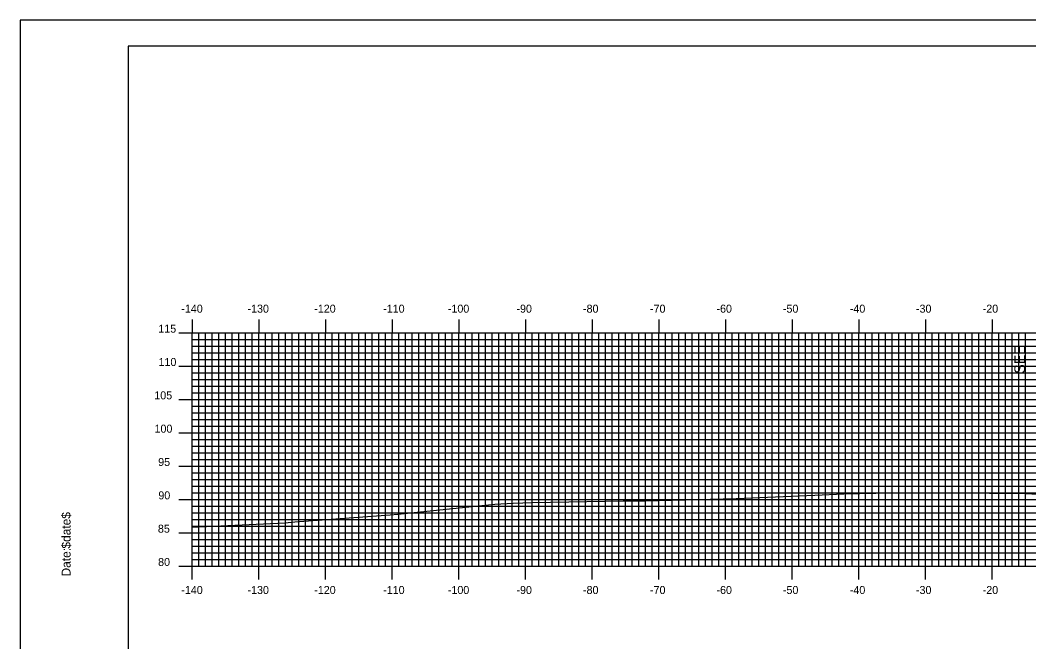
# Model space of a CAD drawing. Extents: x 879 to 1222, y -1658 to -1438.
# Drawn here: x 878.9 to 1030.1, y -1531 to -1437.7 of the extents above; entities that cross this region are included whole.
import ezdxf

# ---------------------------------------------------------------- set-up
doc = ezdxf.new("R2010")
doc.units = 0
for name, color, linetype in [('ANNOTATION', 7, 'Continuous'), ('BORDER', 7, 'Continuous'), ('H_V ANNOTATION', 7, 'Continuous'), ('MAJOR', 7, 'Continuous'), ('MINOR', 7, 'Continuous'), ('PLOT BOUNDARY', 7, 'Continuous'), ('S_Roadway_Centerline', 7, 'Continuous')]:
    doc.layers.add(name, color=color, linetype=linetype)

msp = doc.modelspace()

# ---------------------------------------------------------------- linework, layer by layer
at = {"layer": 'BORDER'}
msp.add_lwpolyline([(895.05, -1651.6), (1215.05, -1651.6), (1215.05, -1441.6), (895.05, -1441.6)], close=True, dxfattribs=at)
at = {"layer": 'MAJOR'}
for p, q in [((904.65, -1482.6), (904.65, -1484.6)), ((914.65, -1482.6), (914.65, -1484.6)), ((924.65, -1482.6), (924.65, -1484.6)), ((934.65, -1482.6), (934.65, -1484.6)), ((944.65, -1482.6), (944.65, -1484.6)), ((954.65, -1482.6), (954.65, -1484.6)), ((964.65, -1482.6), (964.65, -1484.6)), ((974.65, -1482.6), (974.65, -1484.6)), ((984.65, -1482.6), (984.65, -1484.6)), ((994.65, -1482.6), (994.65, -1484.6)), ((1004.65, -1482.6), (1004.65, -1484.6)), ((1014.65, -1482.6), (1014.65, -1484.6)), ((1024.65, -1482.6), (1024.65, -1484.6)), ((902.64, -1484.6), (904.65, -1484.6)), ((904.65, -1484.6), (1184.65, -1484.6)), ((904.65, -1519.6), (904.65, -1484.6)), ((904.65, -1519.6), (904.65, -1484.6)), ((904.65, -1484.6), (1184.65, -1484.6)), ((914.65, -1519.6), (914.65, -1484.6)), ((924.65, -1519.6), (924.65, -1484.6)), ((934.65, -1519.6), (934.65, -1484.6)), ((944.65, -1519.6), (944.65, -1484.6)), ((954.65, -1519.6), (954.65, -1484.6)), ((964.65, -1519.6), (964.65, -1484.6)), ((974.65, -1519.6), (974.65, -1484.6)), ((984.65, -1519.6), (984.65, -1484.6)), ((994.65, -1519.6), (994.65, -1484.6)), ((1004.65, -1519.6), (1004.65, -1484.6)), ((1014.65, -1519.6), (1014.65, -1484.6)), ((1024.65, -1519.6), (1024.65, -1484.6)), ((902.64, -1489.6), (904.65, -1489.6)), ((904.65, -1489.6), (1184.65, -1489.6)), ((902.64, -1494.6), (904.65, -1494.6)), ((904.65, -1494.6), (1184.65, -1494.6)), ((902.64, -1499.6), (904.65, -1499.6)), ((904.65, -1499.6), (1184.65, -1499.6)), ((902.64, -1504.6), (904.65, -1504.6)), ((904.65, -1504.6), (1184.65, -1504.6)), ((902.64, -1509.6), (904.65, -1509.6)), ((904.65, -1509.6), (1184.65, -1509.6)), ((902.64, -1514.6), (904.65, -1514.6)), ((904.65, -1514.6), (1184.65, -1514.6)), ((902.64, -1519.6), (904.65, -1519.6)), ((904.65, -1519.6), (1184.65, -1519.6)), ((904.65, -1519.6), (1184.65, -1519.6)), ((904.65, -1521.61), (904.65, -1519.6)), ((914.65, -1521.61), (914.65, -1519.6)), ((924.65, -1521.61), (924.65, -1519.6)), ((934.65, -1521.61), (934.65, -1519.6)), ((944.65, -1521.61), (944.65, -1519.6)), ((954.65, -1521.61), (954.65, -1519.6)), ((964.65, -1521.61), (964.65, -1519.6)), ((974.65, -1521.61), (974.65, -1519.6)), ((984.65, -1521.61), (984.65, -1519.6)), ((994.65, -1521.61), (994.65, -1519.6)), ((1004.65, -1521.61), (1004.65, -1519.6)), ((1014.65, -1521.61), (1014.65, -1519.6)), ((1024.65, -1521.61), (1024.65, -1519.6))]:
    msp.add_line(p, q, dxfattribs=at)
at = {"layer": 'MINOR'}
for p, q in [((904.65, -1485.6), (1184.65, -1485.6)), ((904.65, -1485.6), (906.65, -1485.6)), ((905.65, -1519.6), (905.65, -1484.6)), ((906.65, -1519.6), (906.65, -1484.6)), ((907.65, -1519.6), (907.65, -1484.6)), ((908.65, -1519.6), (908.65, -1484.6)), ((909.65, -1519.6), (909.65, -1484.6)), ((910.65, -1519.6), (910.65, -1484.6)), ((911.65, -1519.6), (911.65, -1484.6)), ((912.65, -1519.6), (912.65, -1484.6)), ((913.65, -1519.6), (913.65, -1484.6)), ((915.65, -1519.6), (915.65, -1484.6)), ((916.65, -1519.6), (916.65, -1484.6)), ((917.65, -1519.6), (917.65, -1484.6)), ((918.65, -1519.6), (918.65, -1484.6)), ((919.65, -1519.6), (919.65, -1484.6)), ((920.65, -1519.6), (920.65, -1484.6)), ((921.65, -1519.6), (921.65, -1484.6)), ((922.65, -1519.6), (922.65, -1484.6)), ((923.65, -1519.6), (923.65, -1484.6)), ((925.65, -1519.6), (925.65, -1484.6)), ((926.65, -1519.6), (926.65, -1484.6)), ((927.65, -1519.6), (927.65, -1484.6)), ((928.65, -1519.6), (928.65, -1484.6)), ((929.65, -1519.6), (929.65, -1484.6)), ((930.65, -1519.6), (930.65, -1484.6)), ((931.65, -1519.6), (931.65, -1484.6)), ((932.65, -1519.6), (932.65, -1484.6)), ((933.65, -1519.6), (933.65, -1484.6)), ((935.65, -1519.6), (935.65, -1484.6)), ((936.65, -1519.6), (936.65, -1484.6)), ((937.65, -1519.6), (937.65, -1484.6)), ((938.65, -1519.6), (938.65, -1484.6)), ((939.65, -1519.6), (939.65, -1484.6)), ((940.65, -1519.6), (940.65, -1484.6)), ((941.65, -1519.6), (941.65, -1484.6)), ((942.65, -1519.6), (942.65, -1484.6)), ((943.65, -1519.6), (943.65, -1484.6)), ((945.65, -1519.6), (945.65, -1484.6)), ((946.65, -1519.6), (946.65, -1484.6)), ((947.65, -1519.6), (947.65, -1484.6)), ((948.65, -1519.6), (948.65, -1484.6)), ((949.65, -1519.6), (949.65, -1484.6)), ((950.65, -1519.6), (950.65, -1484.6)), ((951.65, -1519.6), (951.65, -1484.6)), ((952.65, -1519.6), (952.65, -1484.6)), ((953.65, -1519.6), (953.65, -1484.6)), ((955.65, -1519.6), (955.65, -1484.6)), ((956.65, -1519.6), (956.65, -1484.6)), ((957.65, -1519.6), (957.65, -1484.6)), ((958.65, -1519.6), (958.65, -1484.6)), ((959.65, -1519.6), (959.65, -1484.6)), ((960.65, -1519.6), (960.65, -1484.6)), ((961.65, -1519.6), (961.65, -1484.6)), ((962.65, -1519.6), (962.65, -1484.6)), ((963.65, -1519.6), (963.65, -1484.6)), ((965.65, -1519.6), (965.65, -1484.6)), ((966.65, -1519.6), (966.65, -1484.6)), ((967.65, -1519.6), (967.65, -1484.6)), ((968.65, -1519.6), (968.65, -1484.6)), ((969.65, -1519.6), (969.65, -1484.6)), ((970.65, -1519.6), (970.65, -1484.6)), ((971.65, -1519.6), (971.65, -1484.6)), ((972.65, -1519.6), (972.65, -1484.6)), ((973.65, -1519.6), (973.65, -1484.6)), ((975.65, -1519.6), (975.65, -1484.6)), ((976.65, -1519.6), (976.65, -1484.6)), ((977.65, -1519.6), (977.65, -1484.6)), ((978.65, -1519.6), (978.65, -1484.6)), ((979.65, -1519.6), (979.65, -1484.6)), ((980.65, -1519.6), (980.65, -1484.6)), ((981.65, -1519.6), (981.65, -1484.6)), ((982.65, -1519.6), (982.65, -1484.6)), ((983.65, -1519.6), (983.65, -1484.6)), ((985.65, -1519.6), (985.65, -1484.6)), ((986.65, -1519.6), (986.65, -1484.6)), ((987.65, -1519.6), (987.65, -1484.6)), ((988.65, -1519.6), (988.65, -1484.6)), ((989.65, -1519.6), (989.65, -1484.6)), ((990.65, -1519.6), (990.65, -1484.6)), ((991.65, -1519.6), (991.65, -1484.6)), ((992.65, -1519.6), (992.65, -1484.6)), ((993.65, -1519.6), (993.65, -1484.6)), ((995.65, -1519.6), (995.65, -1484.6)), ((996.65, -1519.6), (996.65, -1484.6)), ((997.65, -1519.6), (997.65, -1484.6)), ((998.65, -1519.6), (998.65, -1484.6)), ((999.65, -1519.6), (999.65, -1484.6)), ((1000.65, -1519.6), (1000.65, -1484.6)), ((1001.65, -1519.6), (1001.65, -1484.6)), ((1002.65, -1519.6), (1002.65, -1484.6)), ((1003.65, -1519.6), (1003.65, -1484.6)), ((1005.65, -1519.6), (1005.65, -1484.6)), ((1006.65, -1519.6), (1006.65, -1484.6)), ((1007.65, -1519.6), (1007.65, -1484.6)), ((1008.65, -1519.6), (1008.65, -1484.6)), ((1009.65, -1519.6), (1009.65, -1484.6)), ((1010.65, -1519.6), (1010.65, -1484.6)), ((1011.65, -1519.6), (1011.65, -1484.6)), ((1012.65, -1519.6), (1012.65, -1484.6)), ((1013.65, -1519.6), (1013.65, -1484.6)), ((1015.65, -1519.6), (1015.65, -1484.6)), ((1016.65, -1519.6), (1016.65, -1484.6)), ((1017.65, -1519.6), (1017.65, -1484.6)), ((1018.65, -1519.6), (1018.65, -1484.6)), ((1019.65, -1519.6), (1019.65, -1484.6)), ((1020.65, -1519.6), (1020.65, -1484.6)), ((1021.65, -1519.6), (1021.65, -1484.6)), ((1022.65, -1519.6), (1022.65, -1484.6)), ((1023.65, -1519.6), (1023.65, -1484.6)), ((1025.65, -1519.6), (1025.65, -1484.6)), ((1026.65, -1519.6), (1026.65, -1484.6)), ((1027.65, -1519.6), (1027.65, -1484.6)), ((1028.65, -1519.6), (1028.65, -1484.6)), ((1029.65, -1519.6), (1029.65, -1484.6)), ((904.65, -1486.6), (1184.65, -1486.6)), ((904.65, -1486.6), (906.65, -1486.6)), ((904.65, -1487.6), (1184.65, -1487.6)), ((904.65, -1487.6), (906.65, -1487.6)), ((904.65, -1488.6), (1184.65, -1488.6)), ((904.65, -1488.6), (906.65, -1488.6)), ((904.65, -1490.6), (1184.65, -1490.6)), ((904.65, -1490.6), (906.65, -1490.6)), ((904.65, -1491.6), (1184.65, -1491.6)), ((904.65, -1491.6), (906.65, -1491.6)), ((904.65, -1492.6), (1184.65, -1492.6)), ((904.65, -1492.6), (906.65, -1492.6)), ((904.65, -1493.6), (1184.65, -1493.6)), ((904.65, -1493.6), (906.65, -1493.6)), ((904.65, -1495.6), (1184.65, -1495.6)), ((904.65, -1495.6), (906.65, -1495.6)), ((904.65, -1496.6), (1184.65, -1496.6)), ((904.65, -1496.6), (906.65, -1496.6)), ((904.65, -1497.6), (1184.65, -1497.6)), ((904.65, -1497.6), (906.65, -1497.6)), ((904.65, -1498.6), (1184.65, -1498.6)), ((904.65, -1498.6), (906.65, -1498.6)), ((904.65, -1500.6), (1184.65, -1500.6)), ((904.65, -1500.6), (906.65, -1500.6)), ((904.65, -1501.6), (1184.65, -1501.6)), ((904.65, -1501.6), (906.65, -1501.6)), ((904.65, -1502.6), (1184.65, -1502.6)), ((904.65, -1502.6), (906.65, -1502.6)), ((904.65, -1503.6), (1184.65, -1503.6)), ((904.65, -1503.6), (906.65, -1503.6)), ((904.65, -1505.6), (1184.65, -1505.6)), ((904.65, -1505.6), (906.65, -1505.6)), ((904.65, -1506.6), (1184.65, -1506.6)), ((904.65, -1506.6), (906.65, -1506.6)), ((904.65, -1507.6), (1184.65, -1507.6)), ((904.65, -1507.6), (906.65, -1507.6)), ((904.65, -1508.6), (1184.65, -1508.6)), ((904.65, -1508.6), (906.65, -1508.6)), ((904.65, -1510.6), (1184.65, -1510.6)), ((904.65, -1510.6), (906.65, -1510.6)), ((904.65, -1511.6), (1184.65, -1511.6)), ((904.65, -1511.6), (906.65, -1511.6)), ((904.65, -1512.6), (1184.65, -1512.6)), ((904.65, -1512.6), (906.65, -1512.6)), ((904.65, -1513.6), (1184.65, -1513.6)), ((904.65, -1513.6), (906.65, -1513.6)), ((904.65, -1515.6), (1184.65, -1515.6)), ((904.65, -1515.6), (906.65, -1515.6)), ((904.65, -1516.6), (1184.65, -1516.6)), ((904.65, -1516.6), (906.65, -1516.6)), ((904.65, -1517.6), (1184.65, -1517.6)), ((904.65, -1517.6), (906.65, -1517.6)), ((904.65, -1518.6), (1184.65, -1518.6)), ((904.65, -1518.6), (906.65, -1518.6))]:
    msp.add_line(p, q, dxfattribs=at)
at = {"layer": 'PLOT BOUNDARY'}
msp.add_lwpolyline([(878.86, -1657.72), (1218.86, -1657.72), (1218.86, -1437.72), (878.86, -1437.72)], close=True, dxfattribs=at)
at = {"layer": 'S_Roadway_Centerline'}
msp.add_lwpolyline([(904.65, -1513.75), (918.58, -1513.11), (920.07, -1512.98), (934.37, -1511.9), (935.52, -1511.82), (950.04, -1510.34), (952.78, -1510.17), (955.71, -1510.05), (969.3, -1509.84), (972.64, -1509.83), (986.24, -1509.45), (998.05, -1508.96), (1002.38, -1508.78), (1007.22, -1508.65), (1018.83, -1508.63), (1029.58, -1508.74), (1035.48, -1509.02)], dxfattribs=at)

# ---------------------------------------------------------------- texts
at = {"layer": 'ANNOTATION'}
msp.add_text('SEE', height=1.6, rotation=90, dxfattribs=at).set_placement((1029.58, -1490.76))
at = {"layer": 'BORDER'}
for s, p in [('$date$', (886.42, -1516.99)), ('Date:', (886.42, -1521.17))]:
    msp.add_text(s, height=1.339, rotation=90, dxfattribs=at).set_placement(p)
at = {"layer": 'H_V ANNOTATION'}
for s, p in [('-140', (903.03, -1481.6)), ('-130', (912.96, -1481.6)), ('-120', (922.97, -1481.6)), ('-110', (933.31, -1481.6)), ('-100', (943.01, -1481.6)), ('-90', (953.3, -1481.6)), ('-80', (963.28, -1481.6)), ('-70', (973.33, -1481.6)), ('-60', (983.3, -1481.6)), ('-50', (993.26, -1481.6)), ('-40', (1003.3, -1481.6)), ('-30', (1013.22, -1481.6)), ('-20', (1023.23, -1481.6)), ('115', (899.58, -1484.6)), ('110', (899.61, -1489.6)), ('105', (898.98, -1494.6)), ('100', (899.01, -1499.6)), ('95', (899.56, -1504.6)), ('90', (899.59, -1509.6)), ('85', (899.52, -1514.6)), ('80', (899.55, -1519.6)), ('-140', (903.03, -1523.8)), ('-130', (912.96, -1523.8)), ('-120', (922.97, -1523.8)), ('-110', (933.31, -1523.8)), ('-100', (943.01, -1523.8)), ('-90', (953.3, -1523.8)), ('-80', (963.28, -1523.8)), ('-70', (973.33, -1523.8)), ('-60', (983.3, -1523.8)), ('-50', (993.26, -1523.8)), ('-40', (1003.3, -1523.8)), ('-30', (1013.22, -1523.8)), ('-20', (1023.23, -1523.8))]:
    msp.add_text(s, height=1.2, dxfattribs=at).set_placement(p)
at = {"layer": 'MAJOR'}
msp.add_text('-', height=0.012, dxfattribs=at).set_placement((904.64, -1519.6))

doc.saveas('drawing.dxf')
